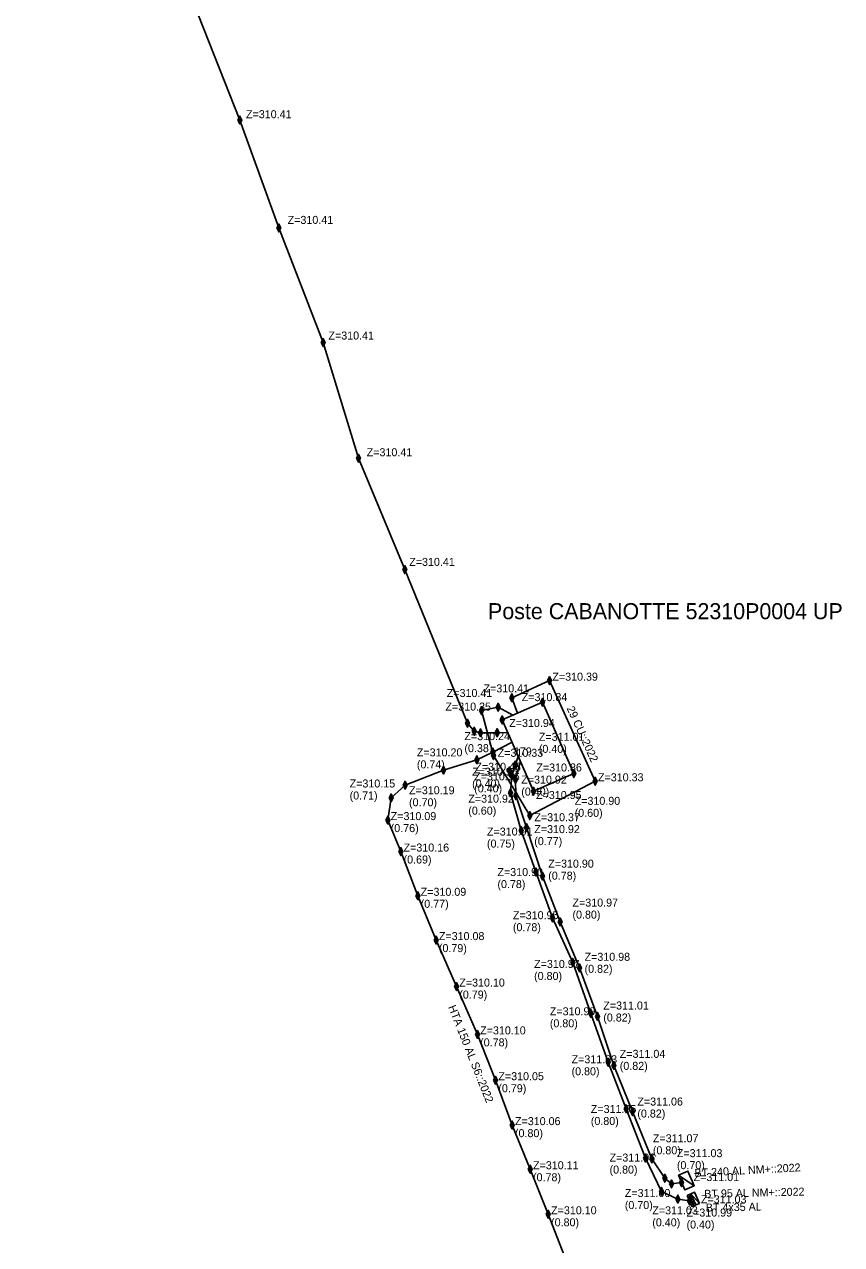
# Model space of a CAD drawing. Extents: x 799271 to 799523, y 67737 to 68184.
# Drawn here: x 799338.3 to 799379.2, y 68011.4 to 68072.4 of the extents above; entities that cross this region are included whole.
import ezdxf

# ---------------------------------------------------------------- set-up
doc = ezdxf.new("R2010")
doc.units = 0
for name, color, linetype in [('PGOC_BRCHT_DI_CONSTRUIT', 7, 'Continuous'), ('PGOC_BRCHT_LR_CONSTRUIT', 7, 'Continuous'), ('PGOC_BT_CONSTRUIT', 7, 'Continuous'), ('PGOC_HTA_CONSTRUIT', 7, 'Continuous'), ('PGOC_POSTE_CONSTRUIT', 7, 'Continuous'), ('PGOC_PTRL', 7, 'Continuous'), ('PGOC_TERRE', 7, 'Continuous')]:
    doc.layers.add(name, color=color, linetype=linetype)

msp = doc.modelspace()

# ---------------------------------------------------------------- linework, layer by layer
at = {"layer": 'PGOC_BRCHT_DI_CONSTRUIT'}
msp.add_line((799372.056, 68013.501), (799371.637, 68013.975), dxfattribs=at)
msp.add_lwpolyline([(799371.637, 68013.975), (799371.872, 68013.423), (799372.056, 68013.501), (799371.821, 68014.053)], close=True, dxfattribs=at)
at = {"layer": 'PGOC_BT_CONSTRUIT'}
msp.add_line((799371.008, 68014.904), (799371.804, 68014.377), dxfattribs=at)
for points in [[(799362.485, 68037.029), (799361.95, 68037.023), (799361.114, 68037.015), (799360.807, 68037.092), (799360.472, 68037.497), (799357.336, 68045.17), (799355.021, 68050.739), (799353.254, 68056.515), (799351.046, 68062.246), (799349.101, 68067.639), (799338.488, 68094.517), (799338.336, 68095.563), (799338.503, 68096.44), (799338.776, 68096.853), (799339.395, 68096.978)], [(799371.57, 68013.621), (799370.981, 68013.713), (799370.17, 68014.099), (799369.372, 68015.764), (799368.391, 68018.225), (799367.506, 68020.556), (799366.633, 68022.989), (799365.733, 68025.537), (799364.713, 68027.769), (799363.89, 68030.067), (799363.161, 68032.127), (799362.628, 68034.02), (799362.679, 68034.876), (799363.008, 68035.833)], [(799363.112, 68035.596), (799362.865, 68034.676), (799362.886, 68033.878), (799363.428, 68032.278), (799364.218, 68029.858), (799365.1, 68027.565), (799366.067, 68025.269), (799366.968, 68022.839), (799367.791, 68020.393), (799368.72, 68018.089), (799369.686, 68015.718), (799370.33, 68014.754), (799370.665, 68014.474), (799371.162, 68014.543)], [(799363.112, 68035.596), (799363.112, 68035.596)], [(799371.511, 68013.812), (799371.658, 68013.875)], [(799371.55, 68013.72), (799371.697, 68013.783)], [(799371.764, 68013.42), (799371.561, 68013.899)], [(799371.589, 68013.628), (799371.736, 68013.691)], [(799371.628, 68013.536), (799371.775, 68013.599)], [(799371.667, 68013.444), (799371.814, 68013.507)]]:
    msp.add_lwpolyline(points, dxfattribs=at)
for points in [[(799371.008, 68014.904), (799371.327, 68014.17), (799371.804, 68014.377), (799371.485, 68015.111)], [(799371.453, 68013.897), (799371.688, 68013.344), (799371.872, 68013.423), (799371.637, 68013.975)]]:
    msp.add_lwpolyline(points, close=True, dxfattribs=at)
at = {"layer": 'PGOC_HTA_CONSTRUIT'}
for points in [[(799362.696, 68036.547), (799361.738, 68036.053), (799360.941, 68035.669), (799359.266, 68035.153), (799357.355, 68034.397), (799356.655, 68033.762), (799356.496, 68032.654), (799357.138, 68031.083), (799357.994, 68028.871), (799358.903, 68026.657), (799359.921, 68024.334), (799360.964, 68021.945), (799361.874, 68019.655), (799362.704, 68017.409), (799363.606, 68015.205), (799364.509, 68012.954), (799365.523, 68010.352)], [(799362.696, 68036.547), (799362.696, 68036.547)], [(799362.696, 68036.547), (799362.696, 68036.547)]]:
    msp.add_lwpolyline(points, dxfattribs=at)
at = {"layer": 'PGOC_POSTE_CONSTRUIT'}
msp.add_lwpolyline([(799363.768, 68034.097), (799365.777, 68034.977), (799364.217, 68038.541), (799362.208, 68037.662), (799363.768, 68034.097)], dxfattribs=at)
at = {"layer": 'PGOC_PTRL'}
for points in [[(799349.001, 68067.639), (799349.101, 68067.839), (799349.201, 68067.639), (799349.101, 68067.439), (799349.001, 68067.639)], [(799349.201, 68067.639), (799349.101, 68067.639), (799349.001, 68067.639)], [(799349.101, 68067.839), (799349.101, 68067.439)], [(799350.946, 68062.246), (799351.046, 68062.446), (799351.146, 68062.246), (799351.046, 68062.046), (799350.946, 68062.246)], [(799351.146, 68062.246), (799351.046, 68062.246), (799350.946, 68062.246)], [(799351.046, 68062.446), (799351.046, 68062.046)], [(799353.154, 68056.515), (799353.254, 68056.715), (799353.354, 68056.515), (799353.254, 68056.315), (799353.154, 68056.515)], [(799353.254, 68056.715), (799353.254, 68056.315)], [(799353.354, 68056.515), (799353.254, 68056.515), (799353.154, 68056.515)], [(799354.921, 68050.739), (799355.021, 68050.939), (799355.121, 68050.739), (799355.021, 68050.539), (799354.921, 68050.739)], [(799355.121, 68050.739), (799355.021, 68050.739), (799354.921, 68050.739)], [(799355.021, 68050.939), (799355.021, 68050.539)], [(799357.236, 68045.17), (799357.336, 68045.37), (799357.436, 68045.17), (799357.336, 68044.97), (799357.236, 68045.17)], [(799357.436, 68045.17), (799357.336, 68045.17), (799357.236, 68045.17)], [(799357.336, 68045.37), (799357.336, 68044.97)], [(799364.471, 68039.622), (799364.571, 68039.822), (799364.671, 68039.622), (799364.571, 68039.422), (799364.471, 68039.622)], [(799364.671, 68039.622), (799364.571, 68039.622), (799364.471, 68039.622)], [(799364.571, 68039.822), (799364.571, 68039.422)], [(799362.593, 68038.771), (799362.693, 68038.971), (799362.793, 68038.771), (799362.693, 68038.571), (799362.593, 68038.771)], [(799362.693, 68038.971), (799362.693, 68038.571)], [(799361.903, 68038.295), (799362.003, 68038.495), (799362.103, 68038.295), (799362.003, 68038.095), (799361.903, 68038.295)], [(799362.003, 68038.495), (799362.003, 68038.095)], [(799362.793, 68038.771), (799362.693, 68038.771), (799362.593, 68038.771)], [(799364.117, 68038.541), (799364.217, 68038.741), (799364.317, 68038.541), (799364.217, 68038.341), (799364.117, 68038.541)], [(799364.317, 68038.541), (799364.217, 68038.541), (799364.117, 68038.541)], [(799364.217, 68038.741), (799364.217, 68038.341)], [(799361.064, 68038.127), (799361.164, 68038.327), (799361.264, 68038.127), (799361.164, 68037.927), (799361.064, 68038.127)], [(799361.264, 68038.127), (799361.164, 68038.127), (799361.064, 68038.127)], [(799361.164, 68038.327), (799361.164, 68037.927)], [(799362.103, 68038.295), (799362.003, 68038.295), (799361.903, 68038.295)], [(799362.108, 68037.662), (799362.208, 68037.862), (799362.308, 68037.662), (799362.208, 68037.462), (799362.108, 68037.662)], [(799362.208, 68037.862), (799362.208, 68037.462)], [(799360.372, 68037.497), (799360.472, 68037.697), (799360.572, 68037.497), (799360.472, 68037.297), (799360.372, 68037.497)], [(799360.572, 68037.497), (799360.472, 68037.497), (799360.372, 68037.497)], [(799360.472, 68037.697), (799360.472, 68037.297)], [(799360.707, 68037.092), (799360.807, 68037.292), (799360.907, 68037.092), (799360.807, 68036.892), (799360.707, 68037.092)], [(799360.807, 68037.292), (799360.807, 68036.892)], [(799361.014, 68037.015), (799361.114, 68037.215), (799361.214, 68037.015), (799361.114, 68036.815), (799361.014, 68037.015)], [(799361.114, 68037.215), (799361.114, 68036.815)], [(799361.85, 68037.023), (799361.95, 68037.223), (799362.05, 68037.023), (799361.95, 68036.823), (799361.85, 68037.023)], [(799361.95, 68037.223), (799361.95, 68036.823)], [(799362.308, 68037.662), (799362.208, 68037.662), (799362.108, 68037.662)], [(799360.907, 68037.092), (799360.807, 68037.092), (799360.707, 68037.092)], [(799361.214, 68037.015), (799361.114, 68037.015), (799361.014, 68037.015)], [(799362.05, 68037.023), (799361.95, 68037.023), (799361.85, 68037.023)], [(799361.638, 68036.053), (799361.738, 68036.253), (799361.838, 68036.053), (799361.738, 68035.853), (799361.638, 68036.053)], [(799361.638, 68036.053), (799361.738, 68036.253), (799361.838, 68036.053), (799361.738, 68035.853), (799361.638, 68036.053)], [(799361.838, 68036.053), (799361.738, 68036.053), (799361.638, 68036.053)], [(799361.838, 68036.053), (799361.738, 68036.053), (799361.638, 68036.053)], [(799361.664, 68035.875), (799361.764, 68036.075), (799361.864, 68035.875), (799361.764, 68035.675), (799361.664, 68035.875)], [(799361.738, 68036.253), (799361.738, 68035.853)], [(799361.738, 68036.253), (799361.738, 68035.853)], [(799361.764, 68036.075), (799361.764, 68035.675)], [(799359.166, 68035.153), (799359.266, 68035.353), (799359.366, 68035.153), (799359.266, 68034.953), (799359.166, 68035.153)], [(799359.266, 68035.353), (799359.266, 68034.953)], [(799360.841, 68035.669), (799360.941, 68035.869), (799361.041, 68035.669), (799360.941, 68035.469), (799360.841, 68035.669)], [(799361.041, 68035.669), (799360.941, 68035.669), (799360.841, 68035.669)], [(799360.941, 68035.869), (799360.941, 68035.469)], [(799361.864, 68035.875), (799361.764, 68035.875), (799361.664, 68035.875)], [(799362.477, 68035.11), (799362.577, 68035.31), (799362.677, 68035.11), (799362.577, 68034.91), (799362.477, 68035.11)], [(799362.577, 68035.31), (799362.577, 68034.91)], [(799362.762, 68035.407), (799362.862, 68035.607), (799362.962, 68035.407), (799362.862, 68035.207), (799362.762, 68035.407)], [(799362.962, 68035.407), (799362.862, 68035.407), (799362.762, 68035.407)], [(799362.862, 68035.607), (799362.862, 68035.207)], [(799359.366, 68035.153), (799359.266, 68035.153), (799359.166, 68035.153)], [(799362.677, 68035.11), (799362.577, 68035.11), (799362.477, 68035.11)], [(799362.579, 68034.876), (799362.679, 68035.076), (799362.779, 68034.876), (799362.679, 68034.676), (799362.579, 68034.876)], [(799362.779, 68034.876), (799362.679, 68034.876), (799362.579, 68034.876)], [(799362.679, 68035.076), (799362.679, 68034.676)], [(799362.765, 68034.676), (799362.865, 68034.876), (799362.965, 68034.676), (799362.865, 68034.476), (799362.765, 68034.676)], [(799362.865, 68034.876), (799362.865, 68034.476)], [(799365.677, 68034.977), (799365.777, 68035.177), (799365.877, 68034.977), (799365.777, 68034.777), (799365.677, 68034.977)], [(799365.877, 68034.977), (799365.777, 68034.977), (799365.677, 68034.977)], [(799365.777, 68035.177), (799365.777, 68034.777)], [(799366.751, 68034.594), (799366.851, 68034.794), (799366.951, 68034.594), (799366.851, 68034.394), (799366.751, 68034.594)], [(799366.851, 68034.794), (799366.851, 68034.394)], [(799357.255, 68034.397), (799357.355, 68034.597), (799357.455, 68034.397), (799357.355, 68034.197), (799357.255, 68034.397)], [(799357.455, 68034.397), (799357.355, 68034.397), (799357.255, 68034.397)], [(799357.355, 68034.597), (799357.355, 68034.197)], [(799362.528, 68034.02), (799362.628, 68034.22), (799362.728, 68034.02), (799362.628, 68033.82), (799362.528, 68034.02)], [(799362.628, 68034.22), (799362.628, 68033.82)], [(799362.965, 68034.676), (799362.865, 68034.676), (799362.765, 68034.676)], [(799363.668, 68034.097), (799363.768, 68034.297), (799363.868, 68034.097), (799363.768, 68033.897), (799363.668, 68034.097)], [(799363.868, 68034.097), (799363.768, 68034.097), (799363.668, 68034.097)], [(799363.768, 68034.297), (799363.768, 68033.897)], [(799366.951, 68034.594), (799366.851, 68034.594), (799366.751, 68034.594)], [(799356.555, 68033.762), (799356.655, 68033.962), (799356.755, 68033.762), (799356.655, 68033.562), (799356.555, 68033.762)], [(799356.755, 68033.762), (799356.655, 68033.762), (799356.555, 68033.762)], [(799356.655, 68033.962), (799356.655, 68033.562)], [(799362.728, 68034.02), (799362.628, 68034.02), (799362.528, 68034.02)], [(799362.786, 68033.878), (799362.886, 68034.078), (799362.986, 68033.878), (799362.886, 68033.678), (799362.786, 68033.878)], [(799362.986, 68033.878), (799362.886, 68033.878), (799362.786, 68033.878)], [(799362.886, 68034.078), (799362.886, 68033.678)], [(799363.481, 68032.881), (799363.581, 68033.081), (799363.681, 68032.881), (799363.581, 68032.681), (799363.481, 68032.881)], [(799363.681, 68032.881), (799363.581, 68032.881), (799363.481, 68032.881)], [(799363.581, 68033.081), (799363.581, 68032.681)], [(799356.396, 68032.654), (799356.496, 68032.854), (799356.596, 68032.654), (799356.496, 68032.454), (799356.396, 68032.654)], [(799356.596, 68032.654), (799356.496, 68032.654), (799356.396, 68032.654)], [(799356.496, 68032.854), (799356.496, 68032.454)], [(799363.061, 68032.127), (799363.161, 68032.327), (799363.261, 68032.127), (799363.161, 68031.927), (799363.061, 68032.127)], [(799363.161, 68032.327), (799363.161, 68031.927)], [(799363.328, 68032.278), (799363.428, 68032.478), (799363.528, 68032.278), (799363.428, 68032.078), (799363.328, 68032.278)], [(799363.528, 68032.278), (799363.428, 68032.278), (799363.328, 68032.278)], [(799363.428, 68032.478), (799363.428, 68032.078)], [(799363.261, 68032.127), (799363.161, 68032.127), (799363.061, 68032.127)], [(799357.038, 68031.083), (799357.138, 68031.283), (799357.238, 68031.083), (799357.138, 68030.883), (799357.038, 68031.083)], [(799357.238, 68031.083), (799357.138, 68031.083), (799357.038, 68031.083)], [(799357.138, 68031.283), (799357.138, 68030.883)], [(799363.79, 68030.067), (799363.89, 68030.267), (799363.99, 68030.067), (799363.89, 68029.867), (799363.79, 68030.067)], [(799363.99, 68030.067), (799363.89, 68030.067), (799363.79, 68030.067)], [(799363.89, 68030.267), (799363.89, 68029.867)], [(799364.118, 68029.858), (799364.218, 68030.058), (799364.318, 68029.858), (799364.218, 68029.658), (799364.118, 68029.858)], [(799364.318, 68029.858), (799364.218, 68029.858), (799364.118, 68029.858)], [(799364.218, 68030.058), (799364.218, 68029.658)], [(799357.894, 68028.871), (799357.994, 68029.071), (799358.094, 68028.871), (799357.994, 68028.671), (799357.894, 68028.871)], [(799358.094, 68028.871), (799357.994, 68028.871), (799357.894, 68028.871)], [(799357.994, 68029.071), (799357.994, 68028.671)], [(799364.613, 68027.769), (799364.713, 68027.969), (799364.813, 68027.769), (799364.713, 68027.569), (799364.613, 68027.769)], [(799364.813, 68027.769), (799364.713, 68027.769), (799364.613, 68027.769)], [(799364.713, 68027.969), (799364.713, 68027.569)], [(799365, 68027.565), (799365.1, 68027.765), (799365.2, 68027.565), (799365.1, 68027.365), (799365, 68027.565)], [(799365.2, 68027.565), (799365.1, 68027.565), (799365, 68027.565)], [(799365.1, 68027.765), (799365.1, 68027.365)], [(799358.803, 68026.657), (799358.903, 68026.857), (799359.003, 68026.657), (799358.903, 68026.457), (799358.803, 68026.657)], [(799358.903, 68026.857), (799358.903, 68026.457)], [(799359.003, 68026.657), (799358.903, 68026.657), (799358.803, 68026.657)], [(799365.633, 68025.537), (799365.733, 68025.737), (799365.833, 68025.537), (799365.733, 68025.337), (799365.633, 68025.537)], [(799365.733, 68025.737), (799365.733, 68025.337)], [(799365.833, 68025.537), (799365.733, 68025.537), (799365.633, 68025.537)], [(799365.967, 68025.269), (799366.067, 68025.469), (799366.167, 68025.269), (799366.067, 68025.069), (799365.967, 68025.269)], [(799366.167, 68025.269), (799366.067, 68025.269), (799365.967, 68025.269)], [(799366.067, 68025.469), (799366.067, 68025.069)], [(799359.821, 68024.334), (799359.921, 68024.534), (799360.021, 68024.334), (799359.921, 68024.134), (799359.821, 68024.334)], [(799360.021, 68024.334), (799359.921, 68024.334), (799359.821, 68024.334)], [(799359.921, 68024.534), (799359.921, 68024.134)], [(799366.533, 68022.989), (799366.633, 68023.189), (799366.733, 68022.989), (799366.633, 68022.789), (799366.533, 68022.989)], [(799366.633, 68023.189), (799366.633, 68022.789)], [(799366.733, 68022.989), (799366.633, 68022.989), (799366.533, 68022.989)], [(799366.868, 68022.839), (799366.968, 68023.039), (799367.068, 68022.839), (799366.968, 68022.639), (799366.868, 68022.839)], [(799367.068, 68022.839), (799366.968, 68022.839), (799366.868, 68022.839)], [(799366.968, 68023.039), (799366.968, 68022.639)], [(799360.864, 68021.945), (799360.964, 68022.145), (799361.064, 68021.945), (799360.964, 68021.745), (799360.864, 68021.945)], [(799361.064, 68021.945), (799360.964, 68021.945), (799360.864, 68021.945)], [(799360.964, 68022.145), (799360.964, 68021.745)], [(799367.406, 68020.556), (799367.506, 68020.756), (799367.606, 68020.556), (799367.506, 68020.356), (799367.406, 68020.556)], [(799367.506, 68020.756), (799367.506, 68020.356)], [(799367.606, 68020.556), (799367.506, 68020.556), (799367.406, 68020.556)], [(799367.691, 68020.393), (799367.791, 68020.593), (799367.891, 68020.393), (799367.791, 68020.193), (799367.691, 68020.393)], [(799367.891, 68020.393), (799367.791, 68020.393), (799367.691, 68020.393)], [(799367.791, 68020.593), (799367.791, 68020.193)], [(799361.774, 68019.655), (799361.874, 68019.855), (799361.974, 68019.655), (799361.874, 68019.455), (799361.774, 68019.655)], [(799361.974, 68019.655), (799361.874, 68019.655), (799361.774, 68019.655)], [(799361.874, 68019.855), (799361.874, 68019.455)], [(799368.291, 68018.225), (799368.391, 68018.425), (799368.491, 68018.225), (799368.391, 68018.025), (799368.291, 68018.225)], [(799368.391, 68018.425), (799368.391, 68018.025)], [(799368.62, 68018.089), (799368.72, 68018.289), (799368.82, 68018.089), (799368.72, 68017.889), (799368.62, 68018.089)], [(799368.72, 68018.289), (799368.72, 68017.889)], [(799368.491, 68018.225), (799368.391, 68018.225), (799368.291, 68018.225)], [(799368.82, 68018.089), (799368.72, 68018.089), (799368.62, 68018.089)], [(799362.604, 68017.409), (799362.704, 68017.609), (799362.804, 68017.409), (799362.704, 68017.209), (799362.604, 68017.409)], [(799362.804, 68017.409), (799362.704, 68017.409), (799362.604, 68017.409)], [(799362.704, 68017.609), (799362.704, 68017.209)], [(799369.272, 68015.764), (799369.372, 68015.964), (799369.472, 68015.764), (799369.372, 68015.564), (799369.272, 68015.764)], [(799369.372, 68015.964), (799369.372, 68015.564)], [(799369.586, 68015.718), (799369.686, 68015.918), (799369.786, 68015.718), (799369.686, 68015.518), (799369.586, 68015.718)], [(799369.686, 68015.918), (799369.686, 68015.518)], [(799363.506, 68015.205), (799363.606, 68015.405), (799363.706, 68015.205), (799363.606, 68015.005), (799363.506, 68015.205)], [(799363.706, 68015.205), (799363.606, 68015.205), (799363.506, 68015.205)], [(799363.606, 68015.405), (799363.606, 68015.005)], [(799369.472, 68015.764), (799369.372, 68015.764), (799369.272, 68015.764)], [(799369.786, 68015.718), (799369.686, 68015.718), (799369.586, 68015.718)], [(799370.23, 68014.754), (799370.33, 68014.954), (799370.43, 68014.754), (799370.33, 68014.554), (799370.23, 68014.754)], [(799370.43, 68014.754), (799370.33, 68014.754), (799370.23, 68014.754)], [(799370.33, 68014.954), (799370.33, 68014.554)], [(799370.565, 68014.474), (799370.665, 68014.674), (799370.765, 68014.474), (799370.665, 68014.274), (799370.565, 68014.474)], [(799370.665, 68014.674), (799370.665, 68014.274)], [(799371.067, 68014.537), (799371.167, 68014.737), (799371.267, 68014.537), (799371.167, 68014.337), (799371.067, 68014.537)], [(799371.167, 68014.737), (799371.167, 68014.337)], [(799370.07, 68014.099), (799370.17, 68014.299), (799370.27, 68014.099), (799370.17, 68013.899), (799370.07, 68014.099)], [(799370.27, 68014.099), (799370.17, 68014.099), (799370.07, 68014.099)], [(799370.17, 68014.299), (799370.17, 68013.899)], [(799370.765, 68014.474), (799370.665, 68014.474), (799370.565, 68014.474)], [(799371.267, 68014.537), (799371.167, 68014.537), (799371.067, 68014.537)], [(799370.881, 68013.713), (799370.981, 68013.913), (799371.081, 68013.713), (799370.981, 68013.513), (799370.881, 68013.713)], [(799371.081, 68013.713), (799370.981, 68013.713), (799370.881, 68013.713)], [(799370.981, 68013.913), (799370.981, 68013.513)], [(799371.47, 68013.621), (799371.57, 68013.821), (799371.67, 68013.621), (799371.57, 68013.421), (799371.47, 68013.621)], [(799371.67, 68013.621), (799371.57, 68013.621), (799371.47, 68013.621)], [(799371.57, 68013.821), (799371.57, 68013.421)], [(799364.409, 68012.954), (799364.509, 68013.154), (799364.609, 68012.954), (799364.509, 68012.754), (799364.409, 68012.954)], [(799364.609, 68012.954), (799364.509, 68012.954), (799364.409, 68012.954)], [(799364.509, 68013.154), (799364.509, 68012.754)]]:
    msp.add_lwpolyline(points, dxfattribs=at)
at = {"layer": 'PGOC_TERRE'}
for points in [[(799362.744, 68037.897), (799362.003, 68038.295), (799361.164, 68038.127), (799361.764, 68035.875), (799363.581, 68032.881), (799366.851, 68034.594), (799364.571, 68039.622), (799362.693, 68038.771), (799362.968, 68037.994)], [(799362.744, 68037.897), (799362.744, 68037.897)]]:
    msp.add_lwpolyline(points, dxfattribs=at)

# ---------------------------------------------------------------- texts
at = {"layer": 'PGOC_BRCHT_LR_CONSTRUIT'}
msp.add_text('BT 4x35 AL', height=0.4, rotation=1.23126, dxfattribs=at).set_placement((799372.382, 68013.085))
at = {"layer": 'PGOC_BT_CONSTRUIT'}
for s, rotation, p in [('BT 240 AL NM+::2022', 3.09569, (799371.822, 68014.817)), ('BT 95 AL NM+::2022', 1.35034, (799372.304, 68013.774))]:
    msp.add_text(s, height=0.4, rotation=rotation, dxfattribs=at).set_placement(p)
at = {"layer": 'PGOC_HTA_CONSTRUIT'}
msp.add_text('HTA 150 AL S6::2022', height=0.4, rotation=291.67598, dxfattribs=at).set_placement((799359.498, 68023.314))
at = {"layer": 'PGOC_POSTE_CONSTRUIT'}
msp.add_text('Poste CABANOTTE 52310P0004 UP', height=0.8, dxfattribs=at).set_placement((799361.498, 68042.695))
at = {"layer": 'PGOC_PTRL'}
for s, p in [('Z=310.41', (799349.405, 68067.731)), ('Z=310.41', (799351.486, 68062.449)), ('Z=310.41', (799353.525, 68056.67)), ('Z=310.41', (799355.436, 68050.837)), ('Z=310.41', (799357.562, 68045.358)), ('Z=310.39', (799364.711, 68039.622)), ('Z=310.41', (799359.436, 68038.805)), ('Z=310.41', (799361.273, 68039.037)), ('Z=310.84', (799363.182, 68038.6)), ('Z=310.35', (799359.37, 68038.127)), ('Z=310.94', (799362.557, 68037.306)), ('Z=310.24', (799360.318, 68036.649)), ('Z=311.01', (799364.037, 68036.615)), ('Z=310.20', (799357.942, 68035.838)), ('(0.38)', (799360.318, 68036.049)), ('Z=310.33', (799361.978, 68035.817)), ('179', (799362.792, 68035.887)), ('(0.40)', (799364.037, 68036.015)), ('(0.74)', (799357.942, 68035.238)), ('Z=310.48', (799360.866, 68035.119)), ('Z=310.86', (799363.911, 68035.084)), ('Z=310.96', (799360.704, 68034.874)), ('(0.40)', (799360.704, 68034.274)), ('Z=310.96', (799360.806, 68034.639)), ('Z=310.92', (799363.158, 68034.477)), ('Z=310.33', (799366.991, 68034.594)), ('Z=310.15', (799354.583, 68034.283)), ('(0.71)', (799354.583, 68033.683)), ('Z=310.19', (799357.552, 68033.944)), ('(0.40)', (799360.806, 68034.039)), ('(0.40)', (799363.158, 68033.877)), ('Z=310.95', (799363.897, 68033.707)), ('(0.70)', (799357.552, 68033.344)), ('Z=310.92', (799360.513, 68033.526)), ('Z=310.90', (799365.826, 68033.417)), ('Z=310.09', (799356.636, 68032.654)), ('(0.60)', (799360.513, 68032.926)), ('Z=310.37', (799363.813, 68032.598)), ('(0.60)', (799365.826, 68032.817)), ('(0.76)', (799356.636, 68032.054)), ('Z=310.91', (799361.444, 68031.881)), ('Z=310.92', (799363.808, 68032.003)), ('(0.75)', (799361.444, 68031.281)), ('(0.77)', (799363.808, 68031.403)), ('Z=310.16', (799357.278, 68031.083)), ('(0.69)', (799357.278, 68030.483)), ('Z=310.90', (799364.506, 68030.278)), ('Z=310.90', (799361.968, 68029.856)), ('(0.78)', (799364.506, 68029.678)), ('Z=310.09', (799358.134, 68028.871)), ('(0.78)', (799361.968, 68029.256)), ('(0.77)', (799358.134, 68028.271)), ('Z=310.97', (799365.717, 68028.331)), ('Z=310.95', (799362.741, 68027.701)), ('(0.80)', (799365.717, 68027.731)), ('(0.78)', (799362.741, 68027.101)), ('Z=310.08', (799359.043, 68026.657)), ('(0.79)', (799359.043, 68026.057)), ('Z=310.97', (799363.8, 68025.265)), ('Z=310.98', (799366.32, 68025.622)), ('(0.80)', (799363.8, 68024.665)), ('(0.82)', (799366.32, 68025.022)), ('Z=310.10', (799360.061, 68024.334)), ('(0.79)', (799360.061, 68023.734)), ('Z=310.99', (799364.586, 68022.899)), ('Z=311.01', (799367.256, 68023.188)), ('(0.80)', (799364.586, 68022.299)), ('(0.82)', (799367.256, 68022.588)), ('Z=310.10', (799361.104, 68021.945)), ('(0.78)', (799361.104, 68021.345)), ('Z=311.03', (799365.671, 68020.501)), ('Z=311.04', (799368.079, 68020.772)), ('Z=310.05', (799362.014, 68019.655)), ('(0.80)', (799365.671, 68019.901)), ('(0.82)', (799368.079, 68020.172)), ('(0.79)', (799362.014, 68019.055)), ('Z=311.05', (799366.633, 68018.017)), ('Z=311.06', (799368.959, 68018.389)), ('Z=310.06', (799362.844, 68017.409)), ('(0.80)', (799366.633, 68017.417)), ('(0.82)', (799368.959, 68017.789)), ('(0.80)', (799362.844, 68016.809)), ('Z=311.07', (799369.733, 68016.552)), ('Z=311.06', (799367.569, 68015.588)), ('(0.80)', (799369.733, 68015.952)), ('Z=311.03', (799370.932, 68015.809)), ('Z=310.11', (799363.746, 68015.205)), ('(0.80)', (799367.569, 68014.988)), ('(0.70)', (799370.932, 68015.209)), ('(0.78)', (799363.746, 68014.605)), ('Z=311.01', (799371.767, 68014.614)), ('Z=311.00', (799368.332, 68013.816)), ('Z=310.10', (799364.649, 68012.954)), ('(0.70)', (799368.332, 68013.216)), ('Z=311.03', (799369.704, 68012.951)), ('Z=311.03', (799372.134, 68013.504)), ('(0.80)', (799364.649, 68012.354)), ('(0.40)', (799369.704, 68012.351)), ('Z=310.99', (799371.415, 68012.841)), ('(0.40)', (799371.415, 68012.241))]:
    msp.add_text(s, height=0.4, dxfattribs=at).set_placement(p)
at = {"layer": 'PGOC_TERRE'}
msp.add_text('29 CU::2022', height=0.4, rotation=294.38558, dxfattribs=at).set_placement((799365.417, 68038.242))

doc.saveas('drawing.dxf')
